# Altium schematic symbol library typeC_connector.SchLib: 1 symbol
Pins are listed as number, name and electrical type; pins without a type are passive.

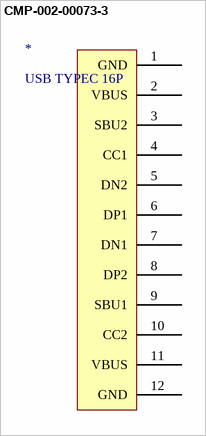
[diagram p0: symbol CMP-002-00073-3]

## CMP-002-00073-3
designator *, comment USB TYPEC 16P
footprint New footprint 1
pins: 1 GND, 2 VBUS, 3 SBU2, 4 CC1, 5 DN2, 6 DP1, 7 DN1, 8 DP2, 9 SBU1, 10 CC2, 11 VBUS, 12 GND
